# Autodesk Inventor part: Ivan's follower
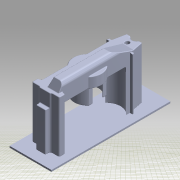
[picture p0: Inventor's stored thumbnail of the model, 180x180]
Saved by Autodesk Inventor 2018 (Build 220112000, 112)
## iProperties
Created: 2013-06
Part Number: Ivan's follower
Material: Generic
Description: STEP AP214
Document SubType Name: Modeling
Designer: johne
Appearance: Generic
Sending System: SolidWorks 2013
Preprocessor: SwSTEP 2.0
Title: Follower.STEP
Author: Asher
Revision Number: ANY
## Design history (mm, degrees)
feature "Body-Move_Copy1"
sketch "Sketch1"
  geometry: L1 (-3.209, -50.521)-(-2.803, -50.521); L2 (-3.615, -53.086)-(-3.615, -50.927); L3 (0.029, -53.518)-(-3.184, -53.518); L4 (7.328, -54.127)-(1.393, -54.127); L5 (11.904, -53.518)-(8.691, -53.518); L6 (12.336, -50.927)-(12.336, -53.086); L7 (11.523, -50.521)-(11.929, -50.521); L8 (11.117, -51.461)-(11.117, -50.448); L9 (4.069, -52.341)-(10.355, -52.341); L10 (3.382, -6.029)-(3.382, -51.575); L11 (9.92, -6.029)-(3.382, -6.029); L12 (8.72, 0)-(9.92, -6.029); L13 (0, 0)-(8.72, 0); L14 (-1.615, -8.121)-(0, 0); L15 (-3.058, -9.082)-(-2.786, -9.082); L16 (-3.735, -10.707)-(-3.481, -9.429); L17 (-2.955, -10.707)-(-3.735, -10.707); L18 (-1.634, -22.35)-(-1.634, -12.028); L19 (-1.634, -34.292)-(-1.634, -49.352); L20 (-3.451, -9.334)-(-1.634, -9.334); L21 (-1.615, -9.334)-(-1.634, -9.334); L22 (-3.137, -7.697)-(-3.137, -7.589); L23 (-3.049, -7.589)-(-1.404, -7.589); L24 (-1.404, -7.589)-(-1.404, -9.334); L25 (-1.404, -9.334)-(-1.615, -9.334); L26 (-4.157, -10.876)-(-3.855, -9.355) reference; L27 (-3.451, -9.334)-(-3.851, -9.334); L28 (-3.851, -9.334)-(-3.363, -7.589); L29 (-3.363, -7.589)-(-3.049, -7.589); L30 (-2.015, -12.028)-(-2.015, -22.35) reference; L31 (-2.015, -12.028)-(-2.015, -9.334); L32 (-2.015, -9.334)-(-4.539, -9.334); L33 (-4.539, -9.334)-(-4.539, -12.028); L34 (-4.539, -12.028)-(-2.015, -12.028); L35 (-2.015, -12.028)-(-2.015, -9.334); A1 r 1.168 centre (-2.803, -49.352) between (-2.803, -50.521) and (-1.634, -49.352); A2 r 0.406 centre (-3.209, -50.927) between (-3.615, -50.927) and (-3.209, -50.521); A3 r 0.432 centre (-3.184, -53.086) between (-3.184, -53.518) and (-3.615, -53.086); A4 r 1.829 centre (0.029, -55.347) between (1.393, -54.127) and (0.029, -53.518); A5 r 1.829 centre (8.691, -55.347) between (8.691, -53.518) and (7.328, -54.127); A6 r 0.432 centre (11.904, -53.086) between (12.336, -53.086) and (11.904, -53.518); A7 r 0.406 centre (11.929, -50.927) between (11.929, -50.521) and (12.336, -50.927); A8 r 1.168 centre (11.523, -49.352) between (11.117, -50.448) and (11.523, -50.521); A9 r 0.432 centre (-3.058, -9.514) between (-3.451, -9.334) and (-3.481, -9.429); A10 r 1.321 centre (-2.955, -12.028) between (-1.634, -12.028) and (-2.955, -10.707); A11 r 0.762 centre (-2.396, -22.35) between (-1.825, -22.854) and (-1.634, -22.35); A12 r 8.255 centre (4.36, -28.321) between (-1.825, -33.788) and (-1.825, -22.854); A13 r 0.762 centre (-2.396, -34.292) between (-1.634, -34.292) and (-1.825, -33.788); A14 r 1.575 centre (4.36, -4.026) between (4.36, -2.451) and (4.36, -5.601); A15 r 1.575 centre (4.36, -4.026) between (4.36, -5.601) and (4.36, -2.451); A16 r 1.194 centre (-2.786, -7.888) between (-2.786, -9.082) and (-1.615, -8.121) reference; A17 r 0.813 centre (-3.058, -9.514) between (-3.058, -8.701) and (-3.855, -9.355) reference; 1 further point
  constraints: 28 end point, 15 centre point, 5 perpendicular, 3 horizontal, 3 point on circle, 2 parallel, 2 point on line, 1 collinear, 1 vertical, 4 other
  dimensions: "d0" = 0.1 distance of L20.start L16.end
extrude "Extrusion1" cut sketch "Sketch1" distance "d3" = 100; taper "d4" = 0 deg
sketch "Sketch2"
  geometry: L1 (-3.209, -50.521)-(-2.803, -50.521); L2 (-3.615, -53.086)-(-3.615, -50.927); L3 (0.029, -53.518)-(-3.184, -53.518); L4 (7.328, -54.127)-(1.393, -54.127); L5 (11.904, -53.518)-(8.691, -53.518); L6 (12.336, -50.927)-(12.336, -53.086); L7 (11.523, -50.521)-(11.929, -50.521); L8 (11.117, -51.461)-(11.117, -50.448); L9 (4.069, -52.341)-(10.355, -52.341); L10 (3.382, -6.029)-(3.382, -51.575); L11 (9.92, -6.029)-(3.382, -6.029); L12 (8.72, 0)-(9.92, -6.029); L13 (0, 0)-(8.72, 0); L14 (-1.615, -8.121)-(0, 0); L15 (-3.058, -9.082)-(-2.786, -9.082); L16 (-3.735, -10.707)-(-3.481, -9.429); L17 (-2.955, -10.707)-(-3.735, -10.707); L18 (-1.634, -22.35)-(-1.634, -12.028); L19 (-1.634, -34.292)-(-1.634, -49.352); L20 (-3.451, -9.334)-(-1.634, -9.334); L21 (-1.615, -9.334)-(-1.634, -9.334); L22 (-3.137, -7.697)-(-3.137, -7.589); L23 (-3.049, -7.589)-(-1.404, -7.589); L24 (-1.404, -7.589)-(-1.404, -9.334); L25 (-1.404, -9.334)-(-1.615, -9.334); L26 (-4.157, -10.876)-(-3.855, -9.355); L27 (-3.451, -9.334)-(-3.851, -9.334); L28 (-3.851, -9.334)-(-3.363, -7.589); L29 (-3.363, -7.589)-(-3.049, -7.589); L30 (-2.015, -12.028)-(-2.015, -22.35); L31 (-2.015, -12.028)-(-2.015, -9.334); L32 (-2.015, -9.334)-(-4.539, -9.334); L33 (-4.539, -9.334)-(-4.539, -12.028); L34 (-4.539, -12.028)-(-2.015, -12.028); L35 (-2.015, -12.028)-(-2.015, -9.334); A1 r 1.168 centre (-2.803, -49.352) between (-2.803, -50.521) and (-1.634, -49.352); A2 r 0.406 centre (-3.209, -50.927) between (-3.615, -50.927) and (-3.209, -50.521); A3 r 0.432 centre (-3.184, -53.086) between (-3.184, -53.518) and (-3.615, -53.086); A4 r 1.829 centre (0.029, -55.347) between (1.393, -54.127) and (0.029, -53.518); A5 r 1.829 centre (8.691, -55.347) between (8.691, -53.518) and (7.328, -54.127); A6 r 0.432 centre (11.904, -53.086) between (12.336, -53.086) and (11.904, -53.518); A7 r 0.406 centre (11.929, -50.927) between (11.929, -50.521) and (12.336, -50.927); A8 r 1.168 centre (11.523, -49.352) between (11.117, -50.448) and (11.523, -50.521); A9 r 0.432 centre (-3.058, -9.514) between (-3.451, -9.334) and (-3.481, -9.429); A10 r 1.321 centre (-2.955, -12.028) between (-1.634, -12.028) and (-2.955, -10.707); A11 r 0.762 centre (-2.396, -22.35) between (-1.825, -22.854) and (-1.634, -22.35); A12 r 8.255 centre (4.36, -28.321) between (-1.825, -33.788) and (-1.825, -22.854); A13 r 0.762 centre (-2.396, -34.292) between (-1.634, -34.292) and (-1.825, -33.788); A14 r 1.575 centre (4.36, -4.026) between (4.36, -2.451) and (4.36, -5.601); A15 r 1.575 centre (4.36, -4.026) between (4.36, -5.601) and (4.36, -2.451); A16 r 1.194 centre (-2.786, -7.888) between (-2.786, -9.082) and (-1.615, -8.121); A17 r 0.813 centre (-3.058, -9.514) between (-3.058, -8.701) and (-3.855, -9.355); 2 further points
  constraints: 70 end point, 35 point on circle, 31 centre point, 5 perpendicular, 3 horizontal, 2 parallel, 2 point on line, 1 collinear, 1 vertical, 8 other
  dimensions: "d5" = 0.1 distance of L20.start L16.end
extrude "Extrusion2" join sketch "Sketch2" stored distance "d6" = 100; taper "d7" = 0 deg
sketch "Sketch3"
  geometry: L1 (-1.51, -7.589)-(-3.363, -7.589) reference; L2 (-3.363, -7.589)-(-3.851, -9.334) reference; L3 (-3.851, -9.334)-(-2.015, -9.334) reference; L4 (-2.015, -9.334)-(-2.015, -11.1) reference; L5 (-1.634, -22.35)-(-1.634, -12.028) reference; L6 (-1.634, -34.292)-(-1.634, -49.352) reference; L7 (-3.209, -50.521)-(-2.803, -50.521) reference; L8 (-3.615, -53.086)-(-3.615, -50.927) reference; L9 (0.029, -53.518)-(-3.184, -53.518) reference; L10 (7.328, -54.127)-(1.393, -54.127) reference; L11 (11.904, -53.518)-(8.691, -53.518) reference; L12 (12.336, -50.927)-(12.336, -53.086) reference; L13 (11.523, -50.521)-(11.929, -50.521) reference; L14 (11.117, -51.461)-(11.117, -50.448) reference; L15 (4.069, -52.341)-(10.355, -52.341) reference; L16 (3.382, -6.029)-(3.382, -51.575) reference; L17 (9.92, -6.029)-(3.382, -6.029) reference; L18 (8.72, 0)-(9.92, -6.029) reference; L19 (0, 0)-(8.72, 0) reference; L20 (-1.51, -7.589)-(0, 0) reference; L21 (-1.634, -22.35)-(-1.634, -12.028) reference; L22 (-2.015, -9.334)-(-1.634, -9.334); L23 (-1.634, -9.334)-(-1.634, -12.525); L24 (-1.634, -12.525)-(-2.015, -12.525); L25 (-2.015, -12.525)-(-2.015, -9.334); A1 r 1.575 centre (4.36, -4.026) between (4.36, -2.451) and (4.36, -5.601) reference; A2 r 1.575 centre (4.36, -4.026) between (4.36, -5.601) and (4.36, -2.451) reference; A3 r 1.321 centre (-2.955, -12.028) between (-1.634, -12.028) and (-2.015, -11.1) reference; A4 r 0.762 centre (-2.396, -22.35) between (-1.825, -22.854) and (-1.634, -22.35) reference; A5 r 8.255 centre (4.36, -28.321) between (-1.825, -22.854) and (-1.825, -33.788) reference; A6 r 0.762 centre (-2.396, -34.292) between (-1.634, -34.292) and (-1.825, -33.788) reference; A7 r 1.168 centre (-2.803, -49.352) between (-2.803, -50.521) and (-1.634, -49.352) reference; A8 r 0.406 centre (-3.209, -50.927) between (-3.209, -50.521) and (-3.615, -50.927) reference; A9 r 0.432 centre (-3.184, -53.086) between (-3.615, -53.086) and (-3.184, -53.518) reference; A10 r 1.829 centre (0.029, -55.347) between (1.393, -54.127) and (0.029, -53.518) reference; A11 r 1.829 centre (8.691, -55.347) between (8.691, -53.518) and (7.328, -54.127) reference; A12 r 0.432 centre (11.904, -53.086) between (11.904, -53.518) and (12.336, -53.086) reference; A13 r 0.406 centre (11.929, -50.927) between (12.336, -50.927) and (11.929, -50.521) reference; A14 r 1.168 centre (11.523, -49.352) between (11.117, -50.448) and (11.523, -50.521) reference; 1 further point
  constraints: 8 end point, 2 parallel, 1 horizontal, 1 perpendicular, 1 point on line, 2 other
extrude "Extrusion3" join sketch "Sketch3" distance "d8" = 2; taper "d9" = 0 deg
fillet "Fillet2" dims "d11" = 0.378
workplane "Work Plane1"
mirror "Mirror1"
mirror "Mirror2"
sketch "Sketch4"
  geometry: L1 (20.057, 23.709)-(-7.294, 23.709); L2 (-7.294, 23.709)-(-7.294, -43.757); L3 (-7.294, -43.757)-(20.057, -43.757); L4 (20.057, -43.757)-(20.057, 23.709); 1 further point
  constraints: 8 end point, 2 parallel, 1 horizontal, 1 perpendicular
extrude "Extrusion4" cut sketch "Sketch4" distance "d12" = 10; taper "d13" = 0 deg
sketch "Sketch5"
  geometry: C1 r 2.54 at (4.36, 1.651); 3 further points; 1 other entity
  constraints: 1 centre point, 1 other
  dimensions: "d14" = 5.08 diameter of C1; "d19" = 1.27 dimension on C1.centre
extrude "Extrusion5" cut sketch "Sketch5" distance "d15" = 50; taper "d16" = 0 deg
sketch "Sketch6"
  geometry: L1 (-3.756, 6.103)-(-3.99, 6.377); L2 (-3.99, 6.377)-(-3.912, 6.901); L3 (-3.912, 6.901)-(-3.463, 6.888); L4 (-3.463, 6.888)-(-3.382, 6.41); A1 r 0.381 centre (-3.382, 6.029) between (-3.382, 6.41) and (-3.756, 6.103) reference; 1 further point
  constraints: 8 end point
extrude "Extrusion6" cut sketch "Sketch6" distance "d17" = 50; taper "d18" = 0 deg
mirror "Mirror3"
fillet "Fillet3" dims "d20" = 1
sketch "Sketch7"
  geometry: L1 (-5.397, -3.305)-(-5.397, -6.496) reference; L2 (-5.397, -3.305)-(-5.397, -2.713); L3 (-5.28, -1.56)-(-6.458, -1.56) reference; L4 (-5.397, -2.713)-(-7.316, -2.713); L5 (-7.316, -2.713)-(-7.316, -4.097); L6 (-7.316, -4.097)-(-5.397, -4.097); L7 (-5.397, -4.097)-(-5.397, -2.713); 1 further point
  constraints: 10 end point, 2 parallel, 1 horizontal, 1 perpendicular, 1 vertical
extrude "Extrusion7" cut sketch "Sketch7" distance "d22" = 50; taper "d23" = 0 deg
mirror "Mirror4"
fillet "Fillet4" dims "d24" = 0.381
fillet "Fillet5" dims "d25" = 2.78
sketch "Sketch8"
  geometry: L1 (-6.375, 3.975)-(-5.923, 3.975); L2 (-5.923, 3.975)-(-6.271, 5.504); A1 r 8.344 centre (0, 0) between (0, 8.344) and (-6.886, 4.712) reference; A2 r 0.787 centre (-7.163, 3.975) between (-6.375, 3.975) and (-6.886, 4.712) reference; 1 further point
  constraints: 4 end point, 1 horizontal, 1 point on circle
extrude "Extrusion8" join sketch "Sketch8" distance "d26" = 3; taper "d27" = 0 deg
mirror "Mirror5"
fillet "Fillet6" dims "d28" = 4.3
fillet "Fillet7" dims "d29" = 0.3
fillet "Fillet8" dims "d30" = 0.3
fillet "Fillet9" dims "d31" = 0.3
fillet "Fillet10" dims "d32" = 0.3
fillet "Fillet11" dims "d33" = 0.3
fillet "Fillet12" dims "d34" = 0.2
sketch "Sketch9"
  geometry: L1 (14.969, 6.397)-(-10.573, 6.397); L2 (-10.573, 6.397)-(-10.573, -66.205); L3 (-10.573, -66.205)-(14.969, -66.205); L4 (14.969, -66.205)-(14.969, 6.397); 1 further point
  constraints: 8 end point, 2 parallel, 1 horizontal, 1 perpendicular
extrude "Extrusion9" join sketch "Sketch9" distance "d35" = 1; taper "d36" = 0 deg
body "Solid1"
node "Projected Loop2"
